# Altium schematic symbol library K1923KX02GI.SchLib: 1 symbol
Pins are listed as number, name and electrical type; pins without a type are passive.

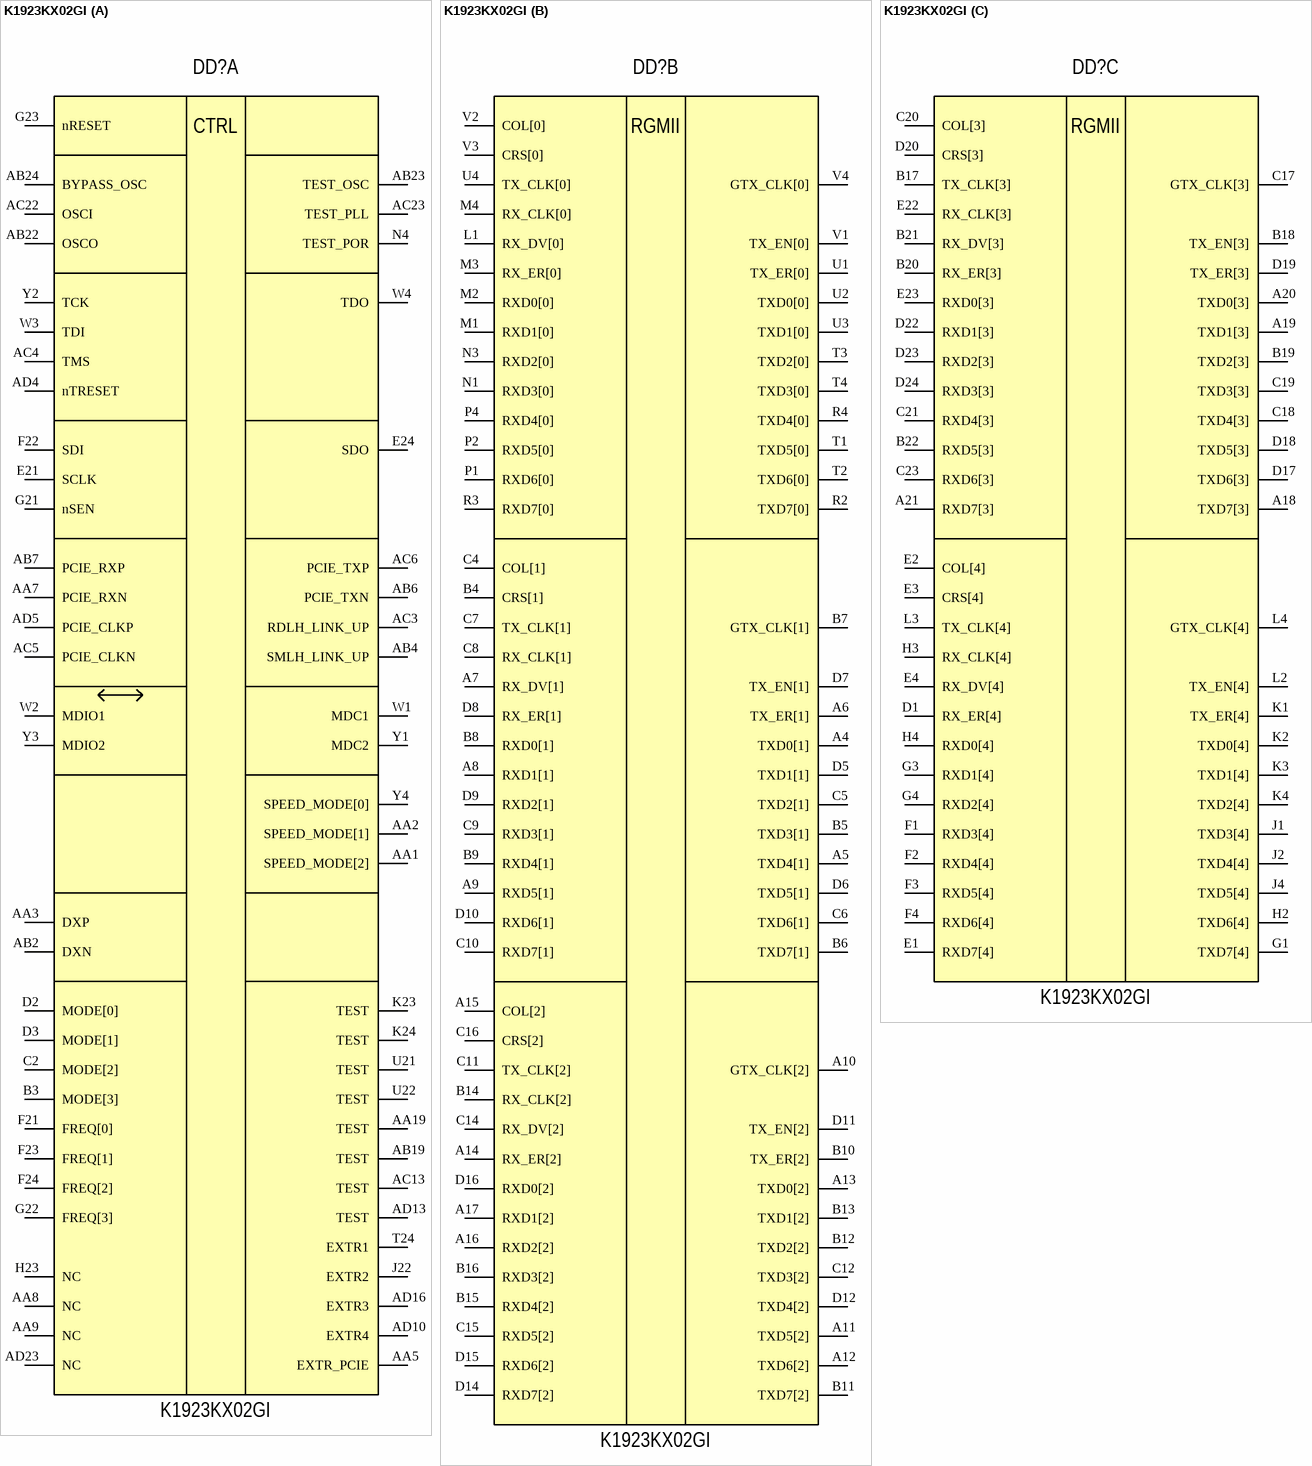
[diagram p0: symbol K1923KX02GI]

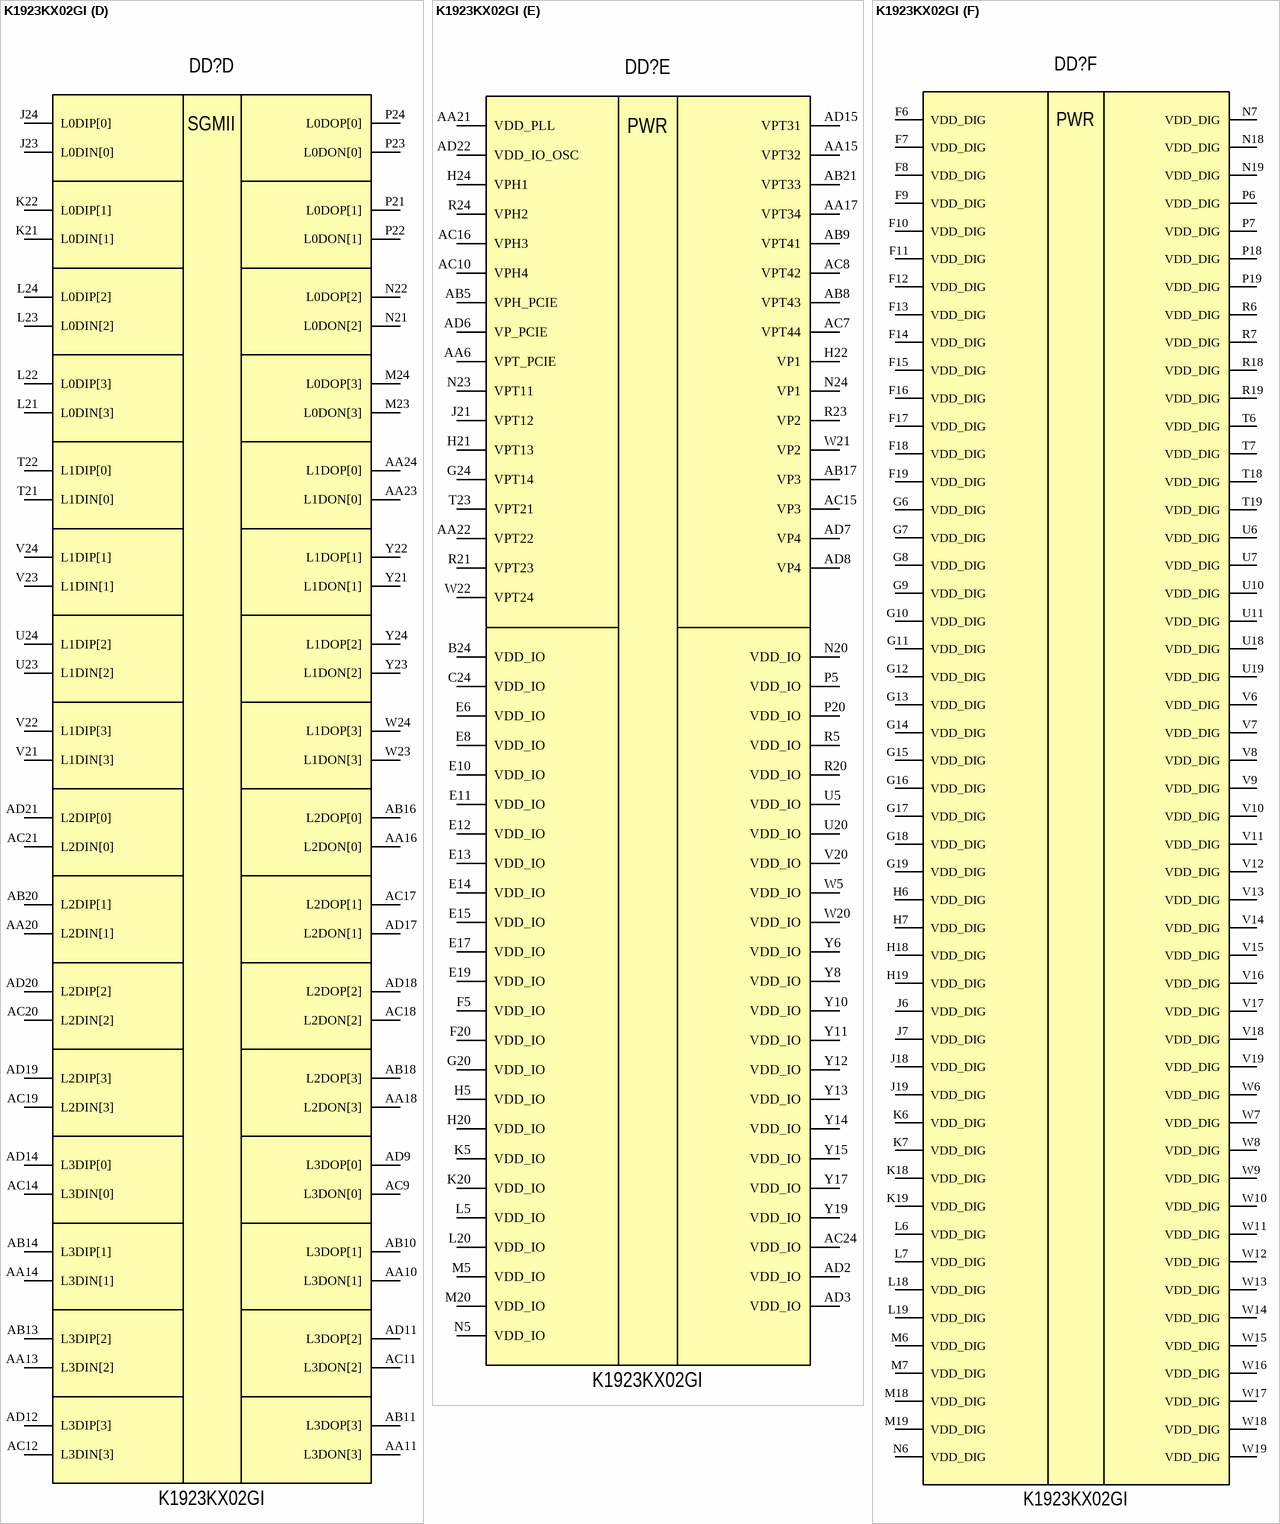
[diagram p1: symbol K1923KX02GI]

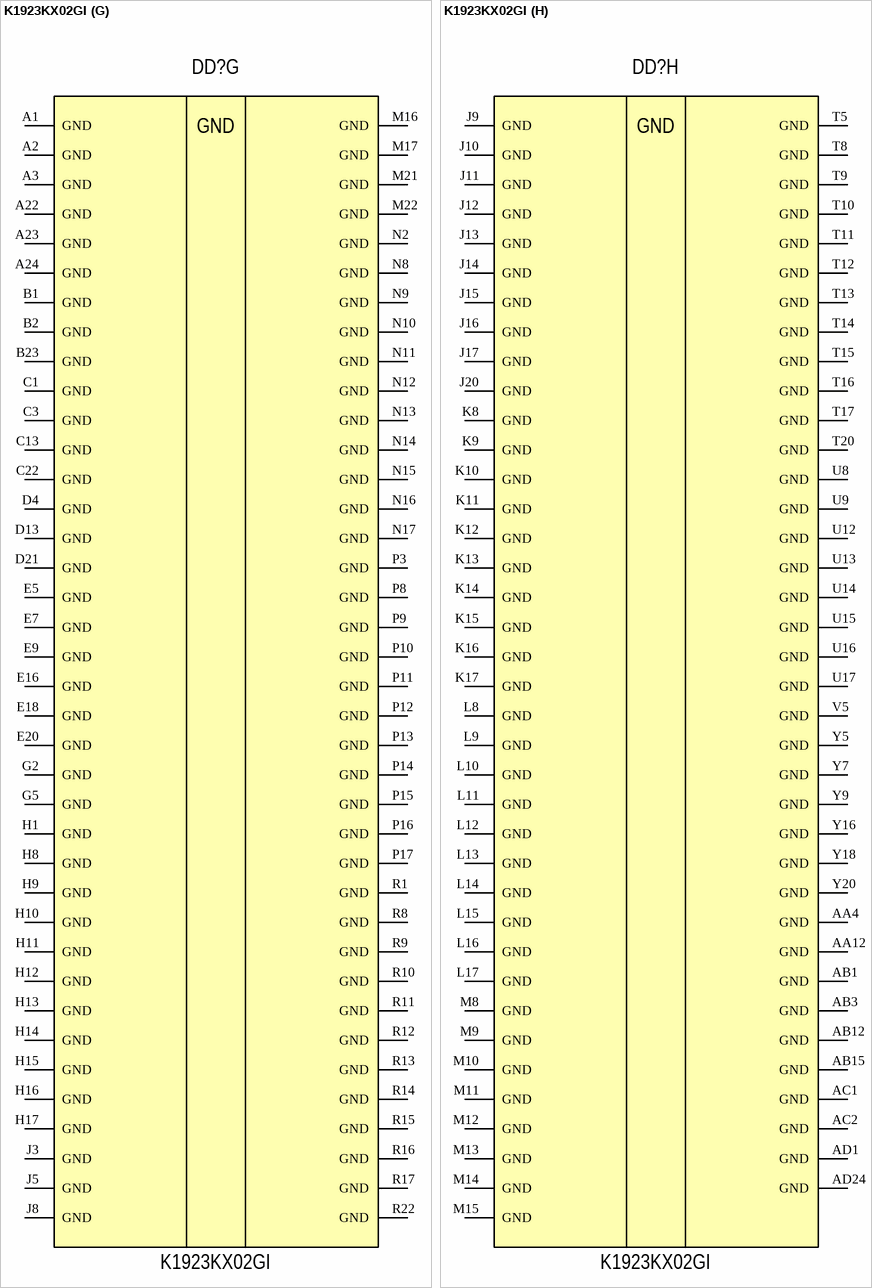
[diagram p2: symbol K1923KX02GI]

## K1923KX02GI
designator DD?
K1923KX02GI_BGA576
part A pins: AA1 SPEED_MODE[2], AA2 SPEED_MODE[1], AA3 DXP, AA5 EXTR_PCIE, AA7 PCIE_RXN, AA8 NC, AA9 NC, AA19 TEST, AB2 DXN, AB4 SMLH_LINK_UP, AB6 PCIE_TXN, AB7 PCIE_RXP, AB19 TEST, AB22 OSCO, AB23 TEST_OSC, AB24 BYPASS_OSC, AC3 RDLH_LINK_UP, AC4 TMS, AC5 PCIE_CLKN, AC6 PCIE_TXP, AC13 TEST, AC22 OSCI, AC23 TEST_PLL, AD4 nTRESET, AD5 PCIE_CLKP, AD10 EXTR4, AD13 TEST, AD16 EXTR3, AD23 NC, B3 MODE[3], C2 MODE[2], D2 MODE[0], D3 MODE[1], E21 SCLK, E24 SDO, F21 FREQ[0], F22 SDI, F23 FREQ[1], F24 FREQ[2], G21 nSEN, G22 FREQ[3], G23 nRESET, H23 NC, J22 EXTR2, K23 TEST, K24 TEST, N4 TEST_POR, T24 EXTR1, U21 TEST, U22 TEST, W1 MDC1, W2 MDIO1, W3 TDI, W4 TDO, Y1 MDC2, Y2 TCK, Y3 MDIO2, Y4 SPEED_MODE[0]
part B pins: A4 TXD0[1], A5 TXD4[1], A6 TX_ER[1], A7 RX_DV[1], A8 RXD1[1], A9 RXD5[1], A10 GTX_CLK[2], A11 TXD5[2], A12 TXD6[2], A13 TXD0[2], A14 RX_ER[2], A15 COL[2], A16 RXD2[2], A17 RXD1[2], B4 CRS[1], B5 TXD3[1], B6 TXD7[1], B7 GTX_CLK[1], B8 RXD0[1], B9 RXD4[1], B10 TX_ER[2], B11 TXD7[2], B12 TXD2[2], B13 TXD1[2], B14 RX_CLK[2], B15 RXD4[2], B16 RXD3[2], C4 COL[1], C5 TXD2[1], C6 TXD6[1], C7 TX_CLK[1], C8 RX_CLK[1], C9 RXD3[1], C10 RXD7[1], C11 TX_CLK[2], C12 TXD3[2], C14 RX_DV[2], C15 RXD5[2], C16 CRS[2], D5 TXD1[1], D6 TXD5[1], D7 TX_EN[1], D8 RX_ER[1], D9 RXD2[1], D10 RXD6[1], D11 TX_EN[2], D12 TXD4[2], D14 RXD7[2], D15 RXD6[2], D16 RXD0[2], L1 RX_DV[0], M1 RXD1[0], M2 RXD0[0], M3 RX_ER[0], M4 RX_CLK[0], N1 RXD3[0], N3 RXD2[0], P1 RXD6[0], P2 RXD5[0], P4 RXD4[0], R2 TXD7[0], R3 RXD7[0], R4 TXD4[0], T1 TXD5[0], T2 TXD6[0], T3 TXD2[0], T4 TXD3[0], U1 TX_ER[0], U2 TXD0[0], U3 TXD1[0], U4 TX_CLK[0], V1 TX_EN[0], V2 COL[0], V3 CRS[0], V4 GTX_CLK[0]
part C pins: A18 TXD7[3], A19 TXD1[3], A20 TXD0[3], A21 RXD7[3], B17 TX_CLK[3], B18 TX_EN[3], B19 TXD2[3], B20 RX_ER[3], B21 RX_DV[3], B22 RXD5[3], C17 GTX_CLK[3], C18 TXD4[3], C19 TXD3[3], C20 COL[3], C21 RXD4[3], C23 RXD6[3], D1 RX_ER[4], D17 TXD6[3], D18 TXD5[3], D19 TX_ER[3], D20 CRS[3], D22 RXD1[3], D23 RXD2[3], D24 RXD3[3], E1 RXD7[4], E2 COL[4], E3 CRS[4], E4 RX_DV[4], E22 RX_CLK[3], E23 RXD0[3], F1 RXD3[4], F2 RXD4[4], F3 RXD5[4], F4 RXD6[4], G1 TXD7[4], G3 RXD1[4], G4 RXD2[4], H2 TXD6[4], H3 RX_CLK[4], H4 RXD0[4], J1 TXD3[4], J2 TXD4[4], J4 TXD5[4], K1 TX_ER[4], K2 TXD0[4], K3 TXD1[4], K4 TXD2[4], L2 TX_EN[4], L3 TX_CLK[4], L4 GTX_CLK[4]
part D pins: AA10 L3DON[1], AA11 L3DON[3], AA13 L3DIN[2], AA14 L3DIN[1], AA16 L2DON[0], AA18 L2DON[3], AA20 L2DIN[1], AA23 L1DON[0], AA24 L1DOP[0], AB10 L3DOP[1], AB11 L3DOP[3], AB13 L3DIP[2], AB14 L3DIP[1], AB16 L2DOP[0], AB18 L2DOP[3], AB20 L2DIP[1], AC9 L3DON[0], AC11 L3DON[2], AC12 L3DIN[3], AC14 L3DIN[0], AC17 L2DOP[1], AC18 L2DON[2], AC19 L2DIN[3], AC20 L2DIN[2], AC21 L2DIN[0], AD9 L3DOP[0], AD11 L3DOP[2], AD12 L3DIP[3], AD14 L3DIP[0], AD17 L2DON[1], AD18 L2DOP[2], AD19 L2DIP[3], AD20 L2DIP[2], AD21 L2DIP[0], J23 L0DIN[0], J24 L0DIP[0], K21 L0DIN[1], K22 L0DIP[1], L21 L0DIN[3], L22 L0DIP[3], L23 L0DIN[2], L24 L0DIP[2], M23 L0DON[3], M24 L0DOP[3], N21 L0DON[2], N22 L0DOP[2], P21 L0DOP[1], P22 L0DON[1], P23 L0DON[0], P24 L0DOP[0], T21 L1DIN[0], T22 L1DIP[0], U23 L1DIN[2], U24 L1DIP[2], V21 L1DIN[3], V22 L1DIP[3], V23 L1DIN[1], V24 L1DIP[1], W23 L1DON[3], W24 L1DOP[3], Y21 L1DON[1], Y22 L1DOP[1], Y23 L1DON[2], Y24 L1DOP[2]
part E pins: AA6 VPT_PCIE, AA15 VPT32, AA17 VPT34, AA21 VDD_PLL, AA22 VPT22, AB5 VPH_PCIE, AB8 VPT43, AB9 VPT41, AB17 VP3, AB21 VPT33, AC7 VPT44, AC8 VPT42, AC10 VPH4, AC15 VP3, AC16 VPH3, AC24 VDD_IO, AD2 VDD_IO, AD3 VDD_IO, AD6 VP_PCIE, AD7 VP4, AD8 VP4, AD15 VPT31, AD22 VDD_IO_OSC, B24 VDD_IO, C24 VDD_IO, E6 VDD_IO, E8 VDD_IO, E10 VDD_IO, E11 VDD_IO, E12 VDD_IO, E13 VDD_IO, E14 VDD_IO, E15 VDD_IO, E17 VDD_IO, E19 VDD_IO, F5 VDD_IO, F20 VDD_IO, G20 VDD_IO, G24 VPT14, H5 VDD_IO, H20 VDD_IO, H21 VPT13, H22 VP1, H24 VPH1, J21 VPT12, K5 VDD_IO, K20 VDD_IO, L5 VDD_IO, L20 VDD_IO, M5 VDD_IO, M20 VDD_IO, N5 VDD_IO, N20 VDD_IO, N23 VPT11, N24 VP1, P5 VDD_IO, P20 VDD_IO, R5 VDD_IO, R20 VDD_IO, R21 VPT23, R23 VP2, R24 VPH2, T23 VPT21, U5 VDD_IO, U20 VDD_IO, V20 VDD_IO, W5 VDD_IO, W20 VDD_IO, W21 VP2, W22 VPT24, Y6 VDD_IO, Y8 VDD_IO, Y10 VDD_IO, Y11 VDD_IO, Y12 VDD_IO, Y13 VDD_IO, Y14 VDD_IO, Y15 VDD_IO, Y17 VDD_IO, Y19 VDD_IO
part F pins: F6 VDD_DIG, F7 VDD_DIG, F8 VDD_DIG, F9 VDD_DIG, F10 VDD_DIG, F11 VDD_DIG, F12 VDD_DIG, F13 VDD_DIG, F14 VDD_DIG, F15 VDD_DIG, F16 VDD_DIG, F17 VDD_DIG, F18 VDD_DIG, F19 VDD_DIG, G6 VDD_DIG, G7 VDD_DIG, G8 VDD_DIG, G9 VDD_DIG, G10 VDD_DIG, G11 VDD_DIG, G12 VDD_DIG, G13 VDD_DIG, G14 VDD_DIG, G15 VDD_DIG, G16 VDD_DIG, G17 VDD_DIG, G18 VDD_DIG, G19 VDD_DIG, H6 VDD_DIG, H7 VDD_DIG, H18 VDD_DIG, H19 VDD_DIG, J6 VDD_DIG, J7 VDD_DIG, J18 VDD_DIG, J19 VDD_DIG, K6 VDD_DIG, K7 VDD_DIG, K18 VDD_DIG, K19 VDD_DIG, L6 VDD_DIG, L7 VDD_DIG, L18 VDD_DIG, L19 VDD_DIG, M6 VDD_DIG, M7 VDD_DIG, M18 VDD_DIG, M19 VDD_DIG, N6 VDD_DIG, N7 VDD_DIG, N18 VDD_DIG, N19 VDD_DIG, P6 VDD_DIG, P7 VDD_DIG, P18 VDD_DIG, P19 VDD_DIG, R6 VDD_DIG, R7 VDD_DIG, R18 VDD_DIG, R19 VDD_DIG, T6 VDD_DIG, T7 VDD_DIG, T18 VDD_DIG, T19 VDD_DIG, U6 VDD_DIG, U7 VDD_DIG, U10 VDD_DIG, U11 VDD_DIG, U18 VDD_DIG, U19 VDD_DIG, V6 VDD_DIG, V7 VDD_DIG, V8 VDD_DIG, V9 VDD_DIG, V10 VDD_DIG, V11 VDD_DIG, V12 VDD_DIG, V13 VDD_DIG, V14 VDD_DIG, V15 VDD_DIG, V16 VDD_DIG, V17 VDD_DIG, V18 VDD_DIG, V19 VDD_DIG, W6 VDD_DIG, W7 VDD_DIG, W8 VDD_DIG, W9 VDD_DIG, W10 VDD_DIG, W11 VDD_DIG, W12 VDD_DIG, W13 VDD_DIG, W14 VDD_DIG, W15 VDD_DIG, W16 VDD_DIG, W17 VDD_DIG, W18 VDD_DIG, W19 VDD_DIG
part G pins: A1 GND, A2 GND, A3 GND, A22 GND, A23 GND, A24 GND, B1 GND, B2 GND, B23 GND, C1 GND, C3 GND, C13 GND, C22 GND, D4 GND, D13 GND, D21 GND, E5 GND, E7 GND, E9 GND, E16 GND, E18 GND, E20 GND, G2 GND, G5 GND, H1 GND, H8 GND, H9 GND, H10 GND, H11 GND, H12 GND, H13 GND, H14 GND, H15 GND, H16 GND, H17 GND, J3 GND, J5 GND, J8 GND, M16 GND, M17 GND, M21 GND, M22 GND, N2 GND, N8 GND, N9 GND, N10 GND, N11 GND, N12 GND, N13 GND, N14 GND, N15 GND, N16 GND, N17 GND, P3 GND, P8 GND, P9 GND, P10 GND, P11 GND, P12 GND, P13 GND, P14 GND, P15 GND, P16 GND, P17 GND, R1 GND, R8 GND, R9 GND, R10 GND, R11 GND, R12 GND, R13 GND, R14 GND, R15 GND, R16 GND, R17 GND, R22 GND
part H pins: AA4 GND, AA12 GND, AB1 GND, AB3 GND, AB12 GND, AB15 GND, AC1 GND, AC2 GND, AD1 GND, AD24 GND, J9 GND, J10 GND, J11 GND, J12 GND, J13 GND, J14 GND, J15 GND, J16 GND, J17 GND, J20 GND, K8 GND, K9 GND, K10 GND, K11 GND, K12 GND, K13 GND, K14 GND, K15 GND, K16 GND, K17 GND, L8 GND, L9 GND, L10 GND, L11 GND, L12 GND, L13 GND, L14 GND, L15 GND, L16 GND, L17 GND, M8 GND, M9 GND, M10 GND, M11 GND, M12 GND, M13 GND, M14 GND, M15 GND, T5 GND, T8 GND, T9 GND, T10 GND, T11 GND, T12 GND, T13 GND, T14 GND, T15 GND, T16 GND, T17 GND, T20 GND, U8 GND, U9 GND, U12 GND, U13 GND, U14 GND, U15 GND, U16 GND, U17 GND, V5 GND, Y5 GND, Y7 GND, Y9 GND, Y16 GND, Y18 GND, Y20 GND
